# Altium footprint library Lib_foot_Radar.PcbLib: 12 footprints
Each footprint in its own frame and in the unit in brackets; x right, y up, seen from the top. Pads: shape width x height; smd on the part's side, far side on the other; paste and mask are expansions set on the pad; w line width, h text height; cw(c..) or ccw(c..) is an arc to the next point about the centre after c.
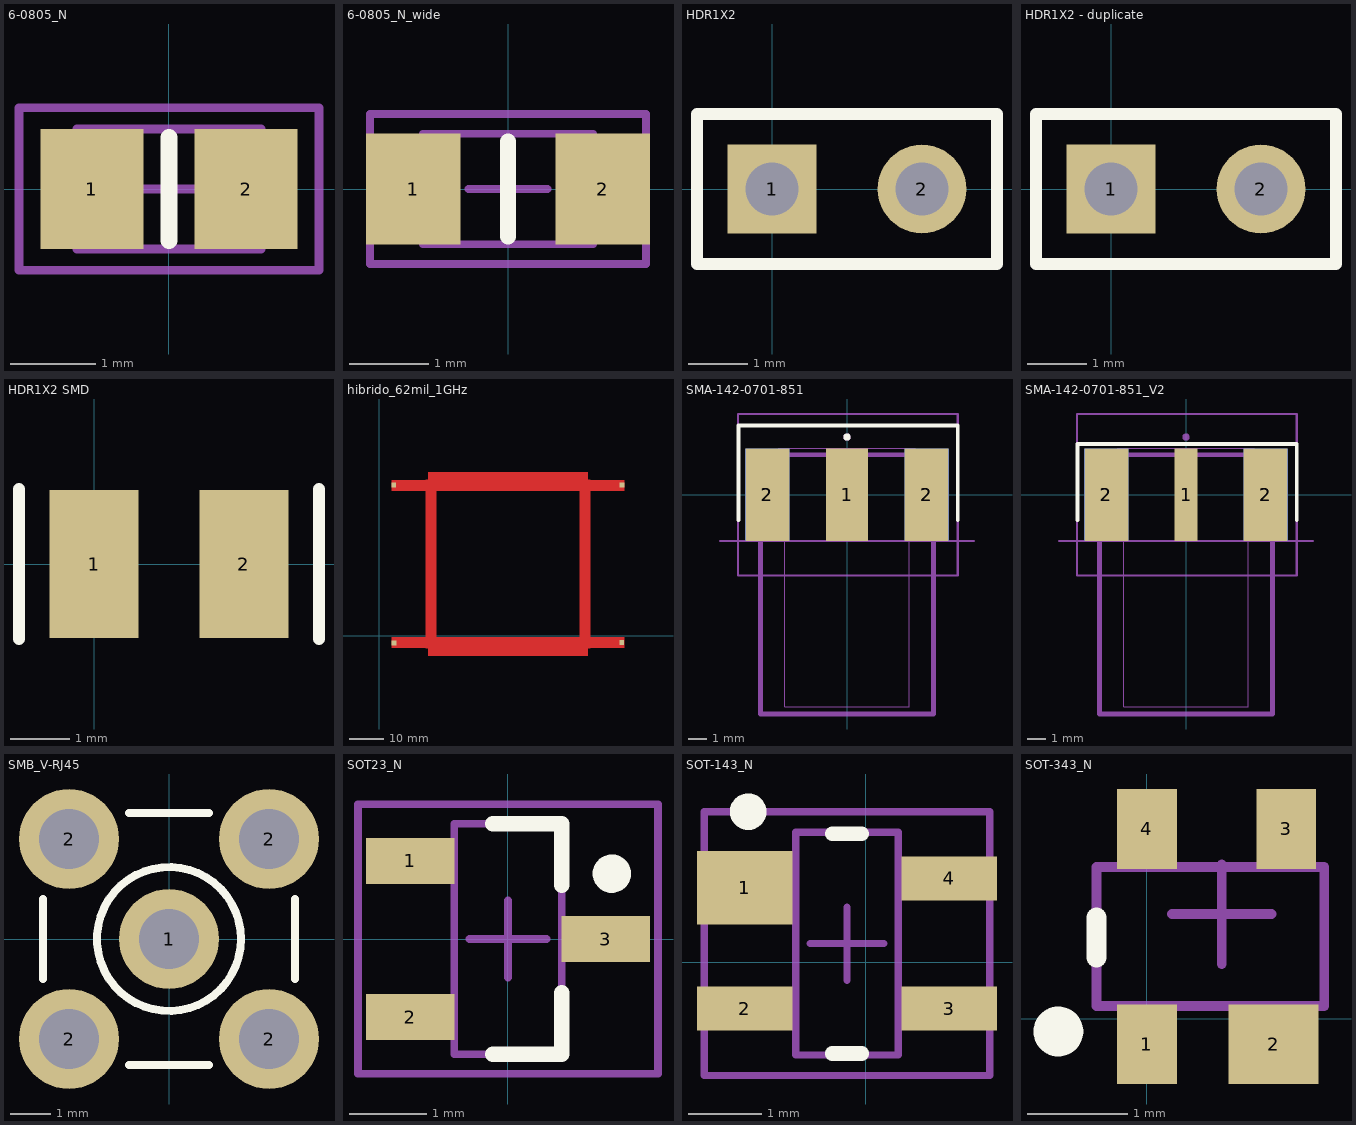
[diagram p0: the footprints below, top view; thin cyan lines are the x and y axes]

## 6-0805_N [mm]
pads (2):
  rect 1.2x1.4 smd: 1(-0.9,0) 2(0.9,0)
Top Overlay:
  lines w0.2: 0,-0.6 0,0.6
Mechanical 13:
  lines w0.1: -1.075,-0.7 1.075,-0.7 1.075,0.7 -1.075,0.7 -1.075,-0.7
Mechanical 15:
  lines w0.1: -0.5,0 0.5,0 ; 0,-0.5 0,0.5 ; -1.75,-0.95 1.75,-0.95 1.75,0.95 -1.75,0.95 -1.75,-0.95
3D body: height 0.7, standoff 0, extent -1.075,-0.7 1.075,0.7

## 6-0805_N_wide [mm]
pads (2):
  rect 1.2x1.4 smd: 1(-1.2,0) 2(1.2,0)
Top Overlay:
  lines w0.2: 0,-0.6 0,0.6
Mechanical 13:
  lines w0.1: -1.075,-0.7 1.075,-0.7 1.075,0.7 -1.075,0.7 -1.075,-0.7
Mechanical 15:
  lines w0.1: -0.5,0 0.5,0 ; 0,-0.5 0,0.5 ; -1.75,-0.95 1.75,-0.95 1.75,0.95 -1.75,0.95 -1.75,-0.95
3D body: height 0.7, standoff 0, extent -1.075,-0.7 1.075,0.7

## HDR1X2 [mm]
pads (2):
  rect 1.5x1.5 hole 0.9: 1(0,0)
  round 1.5 hole 0.9: 2(2.54,0)
Top Overlay:
  lines w0.2: -1.27,-1.27 -1.27,1.27 3.81,1.27 3.81,-1.27 -1.27,-1.27

## HDR1X2 - duplicate [mm]
pads (2):
  rect 1.5x1.5 hole 0.9: 1(0,0)
  round 1.5 hole 0.9: 2(2.54,0)
Top Overlay:
  lines w0.2: -1.27,-1.27 3.81,-1.27 3.81,1.27 -1.27,1.27 -1.27,-1.27

## HDR1X2 SMD [mm]
pads (2):
  rect 1.5x2.5 smd: 1(0,0) 2(2.54,0)
Top Overlay:
  lines w0.2: -1.27,-1.27 -1.27,1.27 ; 3.81,-1.27 3.81,1.27

## hibrido_62mil_1GHz [mm]
pads (4):
  rect 1.43x1.43 smd paste+0 mask+0: 1(4.191,43.84) 2(4.267,-2.108) 3(70.688,43.866) 4(70.612,-1.981)
Top Layer:
  rectangle: 61.473,42.164 71.473,45.364
  rectangle: 61.473,-3.621 71.473,-0.421
  region: 61.473,-0.421 61.473,42.179 58.273,42.179 58.273,-0.421
  region: 13.473,-0.43 3.473,-0.43 3.473,-3.63 13.473,-3.63
  rectangle: 16.673,-5.891 58.273,-0.421
  region: 13.473,45.354 3.473,45.354 3.473,42.154 13.473,42.154
  region: 13.473,42.154 13.473,-0.446 16.673,-0.446 16.673,42.154
  rectangle: 16.673,42.154 58.273,47.624
  region: 61.473,45.364 61.473,42.179 58.273,42.179 58.273,47.624 60.758,47.624 60.758,45.364
  region: 61.473,-3.605 61.473,-0.421 58.258,-0.421 58.258,-5.866 60.758,-5.866 60.758,-3.605
  region: 13.473,-3.63 13.473,-0.446 16.673,-0.446 16.673,-5.891 14.188,-5.891 14.188,-3.63
  region: 13.473,45.339 13.473,42.154 16.688,42.154 16.688,47.6 14.188,47.6 14.188,45.339

## SMA-142-0701-851 [mil] "SMA 50 Ohm, End Launch Jack Receptacle, Tab Contact"
height 312
pads (5):
  rect 90x200 smd: 1(0,0)
  rect 95x200 smd: 2(-172.5,0) 2(172.5,0)
  rect 95x200 smd far side: 2(-172.5,0) 2(172.5,0)
Top Overlay:
  circle w7.87: c0,125 r3.94
  lines w7.87: -235,-55 -235,150 240,150 240,-55
Mechanical 13:
  lines w4: -275,-100 275,-100
  lines w10: -187.5,-474.99 -187.5,87 187.5,87 187.5,-474.99 -187.5,-474.99
  text "PCB EDGE" at 260,-90 h24
Mechanical 15:
  lines w1.97: -147.64,-84.65 -147.64,100.39 147.64,100.39 147.64,-84.65 134.45,-84.65 134.45,-459.45 -134.45,-459.45 -134.45,-84.65 -147.64,-84.65
Mechanical 29:
  circle w7.87: c0,125 r3.94
  lines w5: -236.22,-175 -236.22,175 240.16,175 240.16,-175 -236.22,-175
  text ".Designator" at -95,-5 h19.68
3D body "142-0701-851.stp": height 161, standoff -151, extent -187.5,-474.99 187.5,87

## SMA-142-0701-851_V2 [mil] "SMA 50 Ohm, End Launch Jack Receptacle, Tab Contact"
height 312
pads (5):
  rect 50x200 smd: 1(0,0)
  rect 95x200 smd: 2(-172.5,0) 2(172.5,0)
  rect 95x200 smd far side: 2(-172.5,0) 2(172.5,0)
Top Overlay:
  lines w7.87: -235,-55 -235,110 240,110 240,-55
Mechanical 13:
  lines w4: -275,-100 275,-100
  lines w10: -187.5,-474.99 187.5,-474.99 187.5,87 -187.5,87 -187.5,-474.99
Mechanical 15:
  lines w1.97: -147.64,-84.65 -134.45,-84.65 -134.45,-459.45 134.45,-459.45 134.45,-84.65 147.64,-84.65 147.64,100.39 -147.64,100.39 -147.64,-84.65
Mechanical 29:
  circle w7.87: c0,125 r3.94
  lines w5: -236.22,-175 240.16,-175 240.16,175 -236.22,175 -236.22,-175
  text ".Designator" at -95,-5 h19.68
3D body "142-0701-851.stp": height 161, standoff -151, extent -187.5,-562 187.5,0

## SMB_V-RJ45 [mm]
pads (5):
  round 2.5 hole 1.5: 1(0,0) 2(-2.5,-2.5) 2(-2.5,2.5) 2(2.5,-2.5) 2(2.5,2.5)
Top Overlay:
  circle w0.2: c0,0 r1.8
  lines w0.2: -3.15,-1 -3.15,1 ; -1,-3.15 1,-3.15 ; -1,3.15 1,3.15 ; 3.15,-1 3.15,1
Mechanical 1:
  circle w0.025: c0,0 r0.2
  circle w0.025: c0,0 r1.05
  circle w0.025: c0,0 r1.8

## SOT23_N [mm]
pads (3):
  rect 1.15x0.6 smd: 1(-1.27,1.016) 2(-1.27,-1.016) 3(1.27,0)
Top Overlay:
  circle w0.25: c1.35,0.85 r0.125
  lines w0.2: -0.2,-1.5 0.7,-1.5 0.7,-0.7 ; -0.2,1.5 0.7,1.5 0.7,0.7
Mechanical 13:
  lines w0.1: -0.7,-1.5 -0.7,1.5 0.7,1.5 0.7,-1.5 -0.7,-1.5
Mechanical 15:
  lines w0.1: -0.5,0 0.5,0 ; 0,-0.5 0,0.5 ; -1.95,-1.75 -1.95,1.75 1.95,1.75 1.95,-1.75 -1.95,-1.75
3D body: height 1.1, standoff 0, extent -0.7,-1.5 0.7,1.5

## SOT-143_N [mm] "SOT143, 4-Leads, Body 2.9x1.3mm, Pitch 1.9mm, Lead Span 2.5mm, IPC Medium Density"
height 1.1
pads (4):
  rect 1.3x1 smd: 1(-1.651,1.016)
  rect 1.3x0.6 smd: 2(-1.651,-0.635) 3(1.143,-0.635) 4(1.143,1.143)
Top Overlay:
  circle w0.25: c-1.604,2.054 r0.125
  lines w0.2: -0.454,-1.246 -0.054,-1.246 ; -0.454,1.754 -0.054,1.754
Mechanical 13:
  lines w0.1: -0.954,-1.266 -0.954,1.774 0.446,1.774 0.446,-1.266 -0.954,-1.266
Mechanical 15:
  lines w0.1: -0.754,0.254 0.246,0.254 ; -0.254,-0.246 -0.254,0.754 ; -2.204,-1.546 -2.204,2.054 1.696,2.054 1.696,-1.546 -2.204,-1.546
3D body: height 1.1, standoff 0, extent -0.954,-1.266 0.446,1.774

## SOT-343_N [mm] "SOT143, 4-Leads, Body 2.9x1.3mm, Pitch 1.9mm, Lead Span 2.5mm, IPC Medium Density"
height 1.1
pads (4):
  rect 0.6x0.8 smd: 1(0,-0.254) 3(1.397,1.905) 4(0,1.905)
  rect 0.9x0.8 smd: 2(1.27,-0.254)
Top Overlay:
  circle w0.25: c-0.889,-0.127 r0.125
  lines w0.2: -0.508,0.616 -0.508,1.016
Mechanical 13:
  lines w0.1: -0.508,0.127 1.778,0.127 1.778,1.524 -0.508,1.524 -0.508,0.127
Mechanical 15:
  lines w0.1: 0.25,1.05 1.25,1.05 ; 0.75,0.55 0.75,1.55
3D body: height 1.1, standoff 0, extent -0.508,0.062 1.778,1.462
